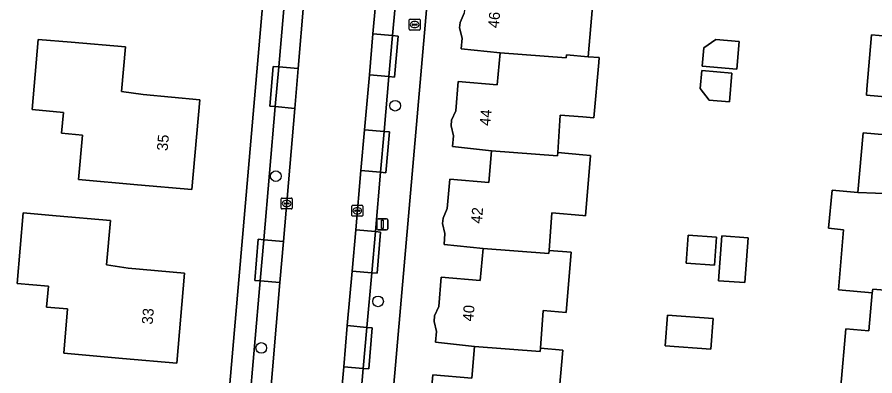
# Model space of a CAD drawing. Extents: x 159626 to 160723, y 388173 to 389416.
# Drawn here: x 159948.2 to 160026.8, y 388526.3 to 388559.2 of the extents above; entities that cross this region are included whole.
import ezdxf

# ---------------------------------------------------------------- set-up
doc = ezdxf.new("R2010")
doc.units = 0
for name, color, linetype in [('IMGEO_Boom', 7, 'Continuous'), ('IMGEO_Brandkraan', 7, 'Continuous'), ('IMGEO_Erf', 7, 'Continuous'), ('IMGEO_Kolk', 7, 'Continuous'), ('IMGEO_Lichtmast', 7, 'Continuous'), ('IMGEO_Pand', 7, 'Continuous'), ('IMGEO_Pand_nummerreeks', 7, 'Continuous'), ('IMGEO_Parkeervlak_open', 7, 'Continuous'), ('IMGEO_Rijbaan_lokaal_gesloten', 7, 'Continuous'), ('IMGEO_Voetpad_open', 7, 'Continuous')]:
    doc.layers.add(name, color=color, linetype=linetype)

msp = doc.modelspace()

# ---------------------------------------------------------------- linework, layer by layer
at = {"layer": 'IMGEO_Boom'}
for centre in [(159982.811, 388551.099), (159971.875, 388544.637), (159981.235, 388533.168), (159970.537, 388528.894)]:
    msp.add_circle(centre, 0.489, dxfattribs=at)
at = {"layer": 'IMGEO_Brandkraan'}
for p, q in [((159984.093, 388558.108), (159984.093, 388558.96)), ((159984.168, 388559.034), (159985.02, 388559.034)), ((159984.352, 388558.528), (159984.352, 388558.54)), ((159984.395, 388558.577), (159984.793, 388558.577)), ((159984.581, 388558.814), (159984.606, 388558.814)), ((159984.836, 388558.54), (159984.836, 388558.528)), ((159985.094, 388558.96), (159985.094, 388558.108)), ((159985.02, 388558.034), (159984.168, 388558.034)), ((159984.79, 388558.491), (159984.392, 388558.491)), ((159984.604, 388558.254), (159984.579, 388558.254))]:
    msp.add_line(p, q, dxfattribs=at)
for points in [[(159984.093, 388558.108), (159984.093, 388558.96)], [(159984.168, 388559.034), (159985.02, 388559.034)], [(159985.094, 388558.96), (159985.094, 388558.108)], [(159985.02, 388558.034), (159984.168, 388558.034)]]:
    msp.add_lwpolyline(points, dxfattribs=at)
for centre, radius, start, end in [((159984.17, 388558.958), 0.0765, 91.55205, 178.44795), ((159984.17, 388558.958), 0.0765, 91.55205, 178.44795), ((159984.392, 388558.537), 0.0403, 85.87752, 175.75265), ((159984.797, 388558.539), 0.0386, 1.73085, 96.63898), ((159985.018, 388558.958), 0.0765, 1.55205, 88.44795), ((159985.018, 388558.958), 0.0765, 1.55205, 88.44795), ((159984.17, 388558.11), 0.0765, 181.55205, 268.44795), ((159984.17, 388558.11), 0.0765, 181.55205, 268.44795), ((159984.389, 388558.527), 0.0366, 178.93798, 274.71019), ((159984.793, 388558.534), 0.043, 264.86636, 352.45326), ((159985.018, 388558.11), 0.0765, 271.55205, 358.44795), ((159985.018, 388558.11), 0.0765, 271.55205, 358.44795)]:
    msp.add_arc(centre, radius, start, end, dxfattribs=at)
for centre, major_axis, ratio, start_param, end_param in [((159984.58, 388558.534), (-0.387, 0.002), 0.722429, 4.712389, 7.853982), ((159984.605, 388558.534), (-0.39, 0.002), 0.717154, 1.570796, 4.712389)]:
    msp.add_ellipse(centre, major_axis=major_axis, ratio=ratio, start_param=start_param, end_param=end_param, dxfattribs=at)
at = {"layer": 'IMGEO_Erf'}
for points in [[(159970.585, 388480.95), (159968.378, 388488.774), (159965.761, 388498.054), (159965.517, 388499.422), (159966.165, 388508.324), (159972.225, 388578.576)], [(159987.091, 388576.032), (159980.714, 388502.802)], [(160000.905, 388560.197), (160000.504, 388555.593), (160001.501, 388555.507), (160001.463, 388555.066), (160001.02, 388549.978), (160000, 388550.067), (159997.932, 388550.247), (159997.711, 388546.803), (160000, 388546.605), (160000.722, 388546.542), (160000.241, 388541.013), (160000, 388541.034), (159997.153, 388541.282), (159996.905, 388537.841), (159998.947, 388537.663), (159998.466, 388532.134), (159996.374, 388532.317), (159996.127, 388528.875), (159998.168, 388528.698), (159997.687, 388523.169)], [(159986.016, 388523.745), (159986.249, 388526.435), (159989.828, 388526.125), (159990.081, 388529.043), (159986.511, 388529.418), (159986.598, 388530.414), (159986.377, 388531.336), (159986.421, 388531.834), (159986.798, 388532.704), (159987.031, 388535.394), (159990.61, 388535.084), (159990.864, 388538.007), (159987.283, 388538.378), (159987.371, 388539.385), (159987.15, 388540.307), (159987.194, 388540.805), (159987.571, 388541.675), (159987.804, 388544.365), (159991.383, 388544.055), (159991.636, 388546.965), (159988.07, 388547.347), (159988.157, 388548.342), (159987.936, 388549.264), (159987.98, 388549.762), (159988.357, 388550.632), (159988.59, 388553.322), (159992.169, 388553.012), (159992.423, 388555.935), (159988.85, 388556.305), (159988.937, 388557.3), (159988.716, 388558.222), (159988.76, 388558.72), (159989.137, 388559.59)], [(160028.078, 388551.893), (160025.986, 388552.075), (160026.033, 388552.614), (160026.466, 388557.595), (160028.559, 388557.414)], [(160034.527, 388515.289), (160024.963, 388516.122), (160025.29, 388519.877), (160023.197, 388520.059), (160023.661, 388525.398), (160024.119, 388530.661), (160026.222, 388530.479), (160026.524, 388533.946), (160023.426, 388534.216), (160023.906, 388539.736), (160022.513, 388539.873), (160022.855, 388543.361), (160025.206, 388543.13), (160025.684, 388548.617), (160027.777, 388548.436)]]:
    msp.add_lwpolyline(points, dxfattribs=at)
for points in [[(159952.402, 388550.487), (159949.529, 388550.741), (159950.097, 388557.179), (159953.117, 388556.918), (159958.098, 388556.487), (159957.721, 388552.411), (159959.706, 388552.129), (159964.893, 388551.651), (159964.178, 388543.415), (159959.198, 388543.855), (159953.79, 388544.332), (159954.149, 388548.402), (159952.233, 388548.571)], [(160011.097, 388556.41), (160012.203, 388557.176), (160014.327, 388556.991), (160014.106, 388554.453), (160010.95, 388554.727)], [(160011.574, 388551.601), (160010.753, 388552.685), (160010.896, 388554.322), (160013.662, 388554.082), (160013.433, 388551.439)], [(159948.732, 388541.272), (159951.738, 388541.012), (159956.719, 388540.581), (159956.342, 388536.505), (159958.327, 388536.223), (159963.514, 388535.745), (159962.799, 388527.5), (159957.819, 388527.937), (159952.429, 388528.409), (159952.785, 388532.478), (159950.87, 388532.646), (159951.038, 388534.561), (159948.166, 388534.812)], [(160012.257, 388539.051), (160012.072, 388536.472), (160009.481, 388536.658), (160009.666, 388539.237)], [(160012.74, 388539.158), (160015.16, 388538.984), (160014.865, 388534.882), (160012.445, 388535.056)], [(160011.946, 388531.611), (160011.744, 388528.798), (160007.563, 388529.098), (160007.764, 388531.911)]]:
    msp.add_lwpolyline(points, close=True, dxfattribs=at)
at = {"layer": 'IMGEO_Kolk'}
for p, q in [((159972.364, 388541.711), (159972.364, 388542.563)), ((159972.439, 388542.637), (159973.291, 388542.637)), ((159972.623, 388542.131), (159972.623, 388542.143)), ((159973.061, 388542.094), (159972.663, 388542.094)), ((159972.666, 388542.18), (159973.064, 388542.18)), ((159972.852, 388542.417), (159972.877, 388542.417)), ((159973.107, 388542.143), (159973.107, 388542.131)), ((159973.365, 388542.563), (159973.365, 388541.711)), ((159973.291, 388541.637), (159972.439, 388541.637)), ((159972.875, 388541.857), (159972.85, 388541.857)), ((159978.834, 388541.046), (159978.834, 388541.898)), ((159978.909, 388541.972), (159979.761, 388541.972)), ((159979.093, 388541.466), (159979.093, 388541.478)), ((159979.531, 388541.429), (159979.133, 388541.429)), ((159979.136, 388541.515), (159979.534, 388541.515)), ((159979.322, 388541.752), (159979.347, 388541.752)), ((159979.577, 388541.478), (159979.577, 388541.466)), ((159979.835, 388541.898), (159979.835, 388541.046)), ((159979.761, 388540.972), (159978.909, 388540.972)), ((159979.345, 388541.192), (159979.32, 388541.192))]:
    msp.add_line(p, q, dxfattribs=at)
for points in [[(159972.364, 388541.711), (159972.364, 388542.563)], [(159972.439, 388542.637), (159973.291, 388542.637)], [(159973.365, 388542.563), (159973.365, 388541.711)], [(159973.291, 388541.637), (159972.439, 388541.637)], [(159978.834, 388541.046), (159978.834, 388541.898)], [(159978.909, 388541.972), (159979.761, 388541.972)], [(159979.835, 388541.898), (159979.835, 388541.046)], [(159979.761, 388540.972), (159978.909, 388540.972)]]:
    msp.add_lwpolyline(points, dxfattribs=at)
for centre, radius, start, end in [((159972.441, 388542.561), 0.0765, 91.55205, 178.44795), ((159972.441, 388542.561), 0.0765, 91.55205, 178.44795), ((159972.663, 388542.14), 0.0403, 85.87752, 175.75265), ((159972.66, 388542.13), 0.0366, 178.93798, 274.71019), ((159973.064, 388542.137), 0.043, 264.86636, 352.45326), ((159973.068, 388542.142), 0.0386, 1.73085, 96.63898), ((159973.289, 388542.561), 0.0765, 1.55205, 88.44795), ((159973.289, 388542.561), 0.0765, 1.55205, 88.44795), ((159972.441, 388541.713), 0.0765, 181.55205, 268.44795), ((159972.441, 388541.713), 0.0765, 181.55205, 268.44795), ((159973.289, 388541.713), 0.0765, 271.55205, 358.44795), ((159973.289, 388541.713), 0.0765, 271.55205, 358.44795), ((159978.911, 388541.896), 0.0765, 91.55205, 178.44795), ((159978.911, 388541.896), 0.0765, 91.55205, 178.44795), ((159979.133, 388541.475), 0.0403, 85.87752, 175.75265), ((159979.13, 388541.465), 0.0366, 178.93798, 274.71019), ((159979.534, 388541.472), 0.043, 264.86636, 352.45326), ((159979.538, 388541.477), 0.0386, 1.73085, 96.63898), ((159979.759, 388541.896), 0.0765, 1.55205, 88.44795), ((159979.759, 388541.896), 0.0765, 1.55205, 88.44795), ((159978.911, 388541.048), 0.0765, 181.55205, 268.44795), ((159978.911, 388541.048), 0.0765, 181.55205, 268.44795), ((159979.759, 388541.048), 0.0765, 271.55205, 358.44795), ((159979.759, 388541.048), 0.0765, 271.55205, 358.44795)]:
    msp.add_arc(centre, radius, start, end, dxfattribs=at)
for centre, major_axis, ratio, start_param, end_param in [((159972.851, 388542.137), (-0.387, 0.002), 0.722429, 4.712389, 7.853982), ((159972.876, 388542.137), (-0.39, 0.002), 0.717154, 1.570796, 4.712389), ((159979.321, 388541.472), (-0.387, 0.002), 0.722429, 4.712389, 7.853982), ((159979.346, 388541.472), (-0.39, 0.002), 0.717154, 1.570796, 4.712389)]:
    msp.add_ellipse(centre, major_axis=major_axis, ratio=ratio, start_param=start_param, end_param=end_param, dxfattribs=at)
at = {"layer": 'IMGEO_Lichtmast'}
for p, q in [((159981.135, 388539.827), (159981.135, 388540.627)), ((159981.135, 388540.627), (159981.135, 388539.827)), ((159981.235, 388540.727), (159982.025, 388540.727)), ((159982.025, 388540.727), (159981.235, 388540.727)), ((159982.125, 388540.627), (159982.125, 388539.827)), ((159982.125, 388539.827), (159982.125, 388540.627)), ((159982.025, 388539.727), (159981.235, 388539.727)), ((159981.235, 388539.727), (159982.025, 388539.727))]:
    msp.add_line(p, q, dxfattribs=at)
msp.add_lwpolyline([(159981.555, 388540.602), (159981.705, 388540.602), (159981.705, 388539.852), (159981.555, 388539.852), (159981.555, 388540.602)], dxfattribs=at)
for centre, start, end in [((159981.235, 388540.627), 90, 180), ((159981.235, 388540.627), 90, 180), ((159982.025, 388540.627), 0, 90), ((159982.025, 388540.627), 360, 90), ((159981.235, 388539.827), 180, 270), ((159981.235, 388539.827), 180, 270), ((159982.025, 388539.827), 270, 0), ((159982.025, 388539.827), 270, 0)]:
    msp.add_arc(centre, 0.1, start, end, dxfattribs=at)
at = {"layer": 'IMGEO_Pand'}
for points in [[(160001.387, 388565.737), (159997.22, 388566.93), (159995.885, 388567.715), (159990.134, 388571.095), (159989.654, 388565.569), (159992.443, 388565.327), (159992.158, 388562.035), (159989.367, 388562.266), (159989.137, 388559.59), (159988.76, 388558.72), (159988.716, 388558.222), (159988.937, 388557.3), (159988.85, 388556.305), (159992.423, 388555.935), (159998.477, 388555.485), (159998.503, 388555.767), (160000.504, 388555.593), (160000.905, 388560.197)], [(160038.604, 388558.53), (160038.376, 388559.484), (160038.46, 388560.448), (160037.324, 388560.547), (160035.77, 388562.476), (160036.828, 388563.366), (160031.991, 388569.166), (160028.349, 388566.128), (160030.408, 388563.647), (160030.093, 388563.385), (160029.897, 388561.194), (160028.896, 388561.281), (160028.559, 388557.414), (160026.466, 388557.595), (160026.033, 388552.614), (160025.986, 388552.075), (160028.078, 388551.893), (160028.18, 388552.188), (160034.086, 388551.708), (160034.354, 388554.784), (160037.94, 388554.471), (160038.171, 388557.131), (160038.561, 388558.032)], [(159959.198, 388543.855), (159964.178, 388543.415), (159964.893, 388551.651), (159959.706, 388552.129), (159957.721, 388552.411), (159958.098, 388556.487), (159953.117, 388556.918), (159950.097, 388557.179), (159949.529, 388550.741), (159952.402, 388550.487), (159952.233, 388548.571), (159954.149, 388548.402), (159953.79, 388544.332)], [(160011.097, 388556.41), (160010.95, 388554.727), (160014.106, 388554.453), (160014.327, 388556.991), (160012.203, 388557.176)], [(159997.711, 388546.803), (159997.932, 388550.247), (160000, 388550.067), (160001.02, 388549.978), (160001.463, 388555.066), (160001.501, 388555.507), (160000.504, 388555.593), (159998.503, 388555.767), (159998.477, 388555.485), (159992.423, 388555.935), (159992.169, 388553.012), (159988.59, 388553.322), (159988.357, 388550.632), (159987.98, 388549.762), (159987.936, 388549.264), (159988.157, 388548.342), (159988.07, 388547.347), (159991.636, 388546.965), (159997.684, 388546.501)], [(160011.574, 388551.601), (160013.433, 388551.439), (160013.662, 388554.082), (160010.896, 388554.322), (160010.753, 388552.685)], [(160037.402, 388548.192), (160037.78, 388549.066), (160037.823, 388549.564), (160037.609, 388550.46), (160037.695, 388551.414), (160034.086, 388551.708), (160028.18, 388552.188), (160028.078, 388551.893), (160027.777, 388548.436), (160025.684, 388548.617), (160025.206, 388543.13), (160033.313, 388542.829), (160033.573, 388545.818), (160037.159, 388545.505)], [(159997.711, 388546.803), (159997.684, 388546.501), (159991.636, 388546.965), (159991.383, 388544.055), (159987.804, 388544.365), (159987.571, 388541.675), (159987.194, 388540.805), (159987.15, 388540.307), (159987.371, 388539.385), (159987.283, 388538.378), (159990.864, 388538.007), (159996.878, 388537.548), (159996.905, 388537.841), (159997.153, 388541.282), (160000, 388541.034), (160000.241, 388541.013), (160000.722, 388546.542), (160000, 388546.605)], [(160036.613, 388539.228), (160036.99, 388540.1), (160037.033, 388540.598), (160036.812, 388541.521), (160036.894, 388542.455), (160033.313, 388542.829), (160025.206, 388543.13), (160022.855, 388543.361), (160022.513, 388539.873), (160023.906, 388539.736), (160023.426, 388534.216), (160026.524, 388533.946), (160026.568, 388534.289), (160032.525, 388533.786), (160032.792, 388536.852), (160036.378, 388536.539)], [(159958.327, 388536.223), (159956.342, 388536.505), (159956.719, 388540.581), (159951.738, 388541.012), (159948.732, 388541.272), (159948.166, 388534.812), (159951.038, 388534.561), (159950.87, 388532.646), (159952.785, 388532.478), (159952.429, 388528.409), (159957.819, 388527.937), (159962.799, 388527.5), (159963.514, 388535.745)], [(160012.257, 388539.051), (160009.666, 388539.237), (160009.481, 388536.658), (160012.072, 388536.472)], [(160012.445, 388535.056), (160014.865, 388534.882), (160015.16, 388538.984), (160012.74, 388539.158)], [(159990.864, 388538.007), (159990.61, 388535.084), (159987.031, 388535.394), (159986.798, 388532.704), (159986.421, 388531.834), (159986.377, 388531.336), (159986.598, 388530.414), (159986.511, 388529.418), (159990.081, 388529.043), (159996.101, 388528.578), (159996.127, 388528.875), (159996.374, 388532.317), (159998.466, 388532.134), (159998.947, 388537.663), (159996.905, 388537.841), (159996.878, 388537.548)], [(160035.829, 388530.233), (160036.206, 388531.104), (160036.249, 388531.602), (160036.029, 388532.522), (160036.112, 388533.483), (160032.525, 388533.786), (160026.568, 388534.289), (160026.524, 388533.946), (160026.222, 388530.479), (160024.119, 388530.661), (160023.661, 388525.398), (160031.736, 388524.73), (160032.01, 388527.876), (160035.03, 388527.612), (160035.596, 388527.563)], [(160011.946, 388531.611), (160007.764, 388531.911), (160007.563, 388529.098), (160011.744, 388528.798)], [(159998.168, 388528.698), (159996.127, 388528.875), (159996.101, 388528.578), (159990.081, 388529.043), (159989.828, 388526.125), (159986.249, 388526.435), (159986.016, 388523.745), (159985.639, 388522.875), (159985.595, 388522.377), (159985.816, 388521.455), (159985.729, 388520.455), (159989.305, 388520.086), (159995.301, 388519.612), (159995.327, 388519.912), (159997.389, 388519.733), (159997.687, 388523.169)]]:
    msp.add_lwpolyline(points, close=True, dxfattribs=at)
at = {"layer": 'IMGEO_Parkeervlak_open'}
for points in [[(159974.969, 388566.874), (159973.209, 388567.051), (159972.136, 388554.658), (159973.918, 388554.507)], [(159983.01, 388562.542), (159981.216, 388562.7), (159980.776, 388557.696), (159982.571, 388557.538)], [(159982.571, 388557.538), (159980.776, 388557.696), (159980.444, 388553.924), (159982.239, 388553.766)], [(159973.918, 388554.507), (159972.136, 388554.658), (159971.82, 388551.013), (159973.608, 388550.858)], [(159982.239, 388553.766), (159980.444, 388553.924), (159980.002, 388548.9), (159981.798, 388548.742)], [(159973.608, 388550.858), (159971.82, 388551.013), (159970.763, 388538.809), (159972.571, 388538.655)], [(159981.798, 388548.742), (159980.002, 388548.9), (159979.672, 388545.154), (159981.469, 388544.996)], [(159981.469, 388544.996), (159979.672, 388545.154), (159979.195, 388539.729), (159980.992, 388539.571)], [(159980.992, 388539.571), (159979.195, 388539.729), (159978.862, 388535.944), (159980.66, 388535.786)], [(159972.571, 388538.655), (159970.763, 388538.809), (159970.437, 388535.043), (159972.25, 388534.886)], [(159980.66, 388535.786), (159978.862, 388535.944), (159978.422, 388530.943), (159980.221, 388530.785)], [(159972.25, 388534.886), (159970.437, 388535.043), (159969.4, 388523.058), (159971.231, 388522.902)], [(159980.221, 388530.785), (159978.422, 388530.943), (159978.09, 388527.172), (159979.889, 388527.014)], [(159979.889, 388527.014), (159978.09, 388527.172), (159977.652, 388522.189), (159979.452, 388522.031)]]:
    msp.add_lwpolyline(points, close=True, dxfattribs=at)
at = {"layer": 'IMGEO_Rijbaan_lokaal_gesloten'}
for points in [[(159974.969, 388566.874), (159973.918, 388554.507), (159973.608, 388550.858), (159972.571, 388538.655), (159972.25, 388534.886), (159971.231, 388522.902), (159970.911, 388519.133), (159969.323, 388500.454), (159969.327, 388500)], [(159975.943, 388502.752), (159976.528, 388509.402), (159976.86, 388513.178), (159977.32, 388518.409), (159977.652, 388522.189), (159978.09, 388527.172), (159978.422, 388530.943), (159978.862, 388535.944), (159979.195, 388539.729), (159979.672, 388545.154), (159980.002, 388548.9), (159980.444, 388553.924), (159980.776, 388557.696), (159981.216, 388562.7)]]:
    msp.add_lwpolyline(points, dxfattribs=at)
at = {"layer": 'IMGEO_Voetpad_open'}
for points in [[(159972.225, 388578.576), (159966.165, 388508.324), (159965.517, 388499.422), (159965.761, 388498.054), (159968.378, 388488.774), (159970.585, 388480.95), (159972.175, 388476.251)], [(159967.432, 388500), (159967.434, 388500.356), (159969.074, 388519.292), (159968.576, 388519.335), (159968.902, 388523.101), (159969.4, 388523.058), (159970.437, 388535.043), (159969.94, 388535.086), (159970.266, 388538.852), (159970.763, 388538.809), (159971.82, 388551.013), (159971.322, 388551.056), (159971.638, 388554.701), (159972.136, 388554.658), (159973.209, 388567.051), (159972.681, 388567.104), (159973.064, 388570.883), (159973.536, 388570.835), (159973.833, 388574.264), (159973.335, 388574.307), (159973.637, 388577.794), (159974.144, 388577.75)], [(159980.714, 388502.802), (159987.091, 388576.032)], [(159983.01, 388562.542), (159982.571, 388557.538), (159983.07, 388557.464), (159982.741, 388553.722), (159982.239, 388553.766), (159981.798, 388548.742), (159982.294, 388548.7), (159981.966, 388544.957), (159981.469, 388544.996), (159980.992, 388539.571), (159981.471, 388539.514), (159981.157, 388535.749), (159980.66, 388535.786), (159980.221, 388530.785), (159980.706, 388530.752), (159980.388, 388526.991), (159979.889, 388527.014), (159979.452, 388522.031)]]:
    msp.add_lwpolyline(points, dxfattribs=at)
for points in [[(159982.239, 388553.766), (159982.741, 388553.722), (159983.07, 388557.464), (159982.571, 388557.538)], [(159972.136, 388554.658), (159971.638, 388554.701), (159971.322, 388551.056), (159971.82, 388551.013)], [(159981.469, 388544.996), (159981.966, 388544.957), (159982.294, 388548.7), (159981.798, 388548.742)], [(159980.66, 388535.786), (159981.157, 388535.749), (159981.471, 388539.514), (159980.992, 388539.571)], [(159970.763, 388538.809), (159970.266, 388538.852), (159969.94, 388535.086), (159970.437, 388535.043)], [(159979.889, 388527.014), (159980.388, 388526.991), (159980.706, 388530.752), (159980.221, 388530.785)]]:
    msp.add_lwpolyline(points, close=True, dxfattribs=at)

# ---------------------------------------------------------------- texts
at = {"layer": 'IMGEO_Pand_nummerreeks'}
for s, rotation, p in [('46', 85.04413, (159992.305, 388558.179)), ('44', 85.02612, (159991.526, 388549.227)), ('35', 85.03836, (159961.953, 388546.928)), ('42', 85.02654, (159990.74, 388540.261)), ('40', 85.02695, (159989.967, 388531.302)), ('33', 85.04375, (159960.574, 388531.017))]:
    msp.add_text(s, height=1, rotation=rotation, dxfattribs=at).set_placement(p)

doc.saveas('drawing.dxf')
